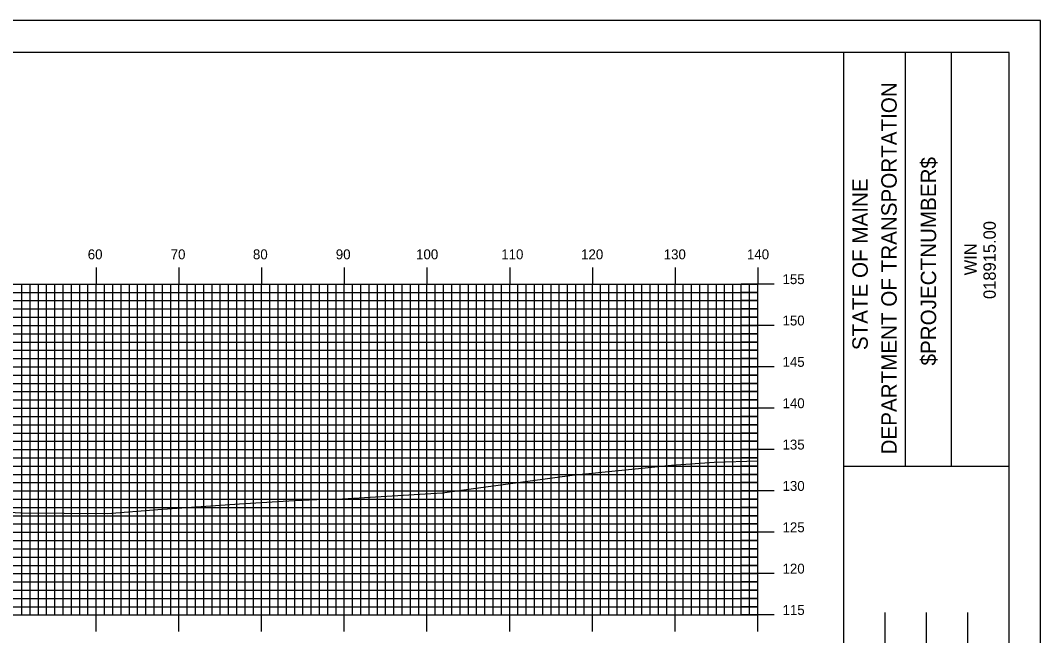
# Model space of a CAD drawing. Extents: x 851360 to 851703, y 364661 to 364881.
# Drawn here: x 851576.6 to 851699.9, y 364806.9 to 364881.3 of the extents above; entities that cross this region are included whole.
import ezdxf

# ---------------------------------------------------------------- set-up
doc = ezdxf.new("R2010")
doc.units = 0
for name, color, linetype in [('BORDER', 7, 'Continuous'), ('H_V ANNOTATION', 7, 'Continuous'), ('MAJOR', 7, 'Continuous'), ('MINOR', 7, 'Continuous'), ('PLOT BOUNDARY', 7, 'Continuous'), ('S_Roadway_Centerline', 7, 'Continuous')]:
    doc.layers.add(name, color=color, linetype=linetype)

msp = doc.modelspace()

# ---------------------------------------------------------------- linework, layer by layer
at = {"layer": 'BORDER'}
for p, q in [((851676.13, 364667.37), (851676.13, 364877.37)), ((851683.59, 364827.36), (851683.59, 364877.36)), ((851689.18, 364827.36), (851689.18, 364877.36)), ((851676.13, 364827.36), (851696.13, 364827.36)), ((851681.13, 364792.38), (851681.13, 364809.67)), ((851686.13, 364792.38), (851686.13, 364809.67)), ((851691.13, 364792.38), (851691.13, 364809.67))]:
    msp.add_line(p, q, dxfattribs=at)
msp.add_lwpolyline([(851376.13, 364667.37), (851696.13, 364667.37), (851696.13, 364877.37), (851376.13, 364877.37)], close=True, dxfattribs=at)
at = {"layer": 'MAJOR'}
for p, q in [((851585.73, 364851.37), (851585.73, 364849.37)), ((851595.73, 364851.37), (851595.73, 364849.37)), ((851605.73, 364851.37), (851605.73, 364849.37)), ((851615.73, 364851.37), (851615.73, 364849.37)), ((851625.73, 364851.37), (851625.73, 364849.37)), ((851635.73, 364851.37), (851635.73, 364849.37)), ((851645.73, 364851.37), (851645.73, 364849.37)), ((851655.73, 364851.37), (851655.73, 364849.37)), ((851665.73, 364851.37), (851665.73, 364849.37)), ((851385.73, 364849.37), (851665.73, 364849.37)), ((851385.73, 364849.37), (851665.73, 364849.37)), ((851585.73, 364809.37), (851585.73, 364849.37)), ((851595.73, 364809.37), (851595.73, 364849.37)), ((851605.73, 364809.37), (851605.73, 364849.37)), ((851615.73, 364809.37), (851615.73, 364849.37)), ((851625.73, 364809.37), (851625.73, 364849.37)), ((851635.73, 364809.37), (851635.73, 364849.37)), ((851645.73, 364809.37), (851645.73, 364849.37)), ((851655.73, 364809.37), (851655.73, 364849.37)), ((851667.73, 364849.37), (851663.72, 364849.37)), ((851665.73, 364809.37), (851665.73, 364849.37)), ((851665.73, 364809.37), (851665.73, 364849.37)), ((851385.73, 364844.37), (851665.73, 364844.37)), ((851667.73, 364844.37), (851663.72, 364844.37)), ((851385.73, 364839.37), (851665.73, 364839.37)), ((851667.73, 364839.37), (851663.72, 364839.37)), ((851385.73, 364834.37), (851665.73, 364834.37)), ((851667.73, 364834.37), (851663.72, 364834.37)), ((851385.73, 364829.37), (851665.73, 364829.37)), ((851667.73, 364829.37), (851663.72, 364829.37)), ((851385.73, 364824.37), (851665.73, 364824.37)), ((851667.73, 364824.37), (851663.72, 364824.37)), ((851385.73, 364819.37), (851665.73, 364819.37)), ((851667.73, 364819.37), (851663.72, 364819.37)), ((851385.73, 364814.37), (851665.73, 364814.37)), ((851667.73, 364814.37), (851663.72, 364814.37)), ((851385.73, 364809.37), (851665.73, 364809.37)), ((851385.73, 364809.37), (851665.73, 364809.37)), ((851585.73, 364807.37), (851585.73, 364809.37)), ((851595.73, 364807.37), (851595.73, 364809.37)), ((851605.73, 364807.37), (851605.73, 364809.37)), ((851615.73, 364807.37), (851615.73, 364809.37)), ((851625.73, 364807.37), (851625.73, 364809.37)), ((851635.73, 364807.37), (851635.73, 364809.37)), ((851645.73, 364807.37), (851645.73, 364809.37)), ((851655.73, 364807.37), (851655.73, 364809.37)), ((851667.73, 364809.37), (851663.72, 364809.37)), ((851665.73, 364807.37), (851665.73, 364809.37))]:
    msp.add_line(p, q, dxfattribs=at)
at = {"layer": 'MINOR'}
for p, q in [((851385.73, 364848.37), (851665.73, 364848.37)), ((851576.73, 364809.37), (851576.73, 364849.37)), ((851577.73, 364809.37), (851577.73, 364849.37)), ((851578.73, 364809.37), (851578.73, 364849.37)), ((851579.73, 364809.37), (851579.73, 364849.37)), ((851580.73, 364809.37), (851580.73, 364849.37)), ((851581.73, 364809.37), (851581.73, 364849.37)), ((851582.73, 364809.37), (851582.73, 364849.37)), ((851583.73, 364809.37), (851583.73, 364849.37)), ((851584.73, 364809.37), (851584.73, 364849.37)), ((851586.73, 364809.37), (851586.73, 364849.37)), ((851587.73, 364809.37), (851587.73, 364849.37)), ((851588.73, 364809.37), (851588.73, 364849.37)), ((851589.73, 364809.37), (851589.73, 364849.37)), ((851590.73, 364809.37), (851590.73, 364849.37)), ((851591.73, 364809.37), (851591.73, 364849.37)), ((851592.73, 364809.37), (851592.73, 364849.37)), ((851593.73, 364809.37), (851593.73, 364849.37)), ((851594.73, 364809.37), (851594.73, 364849.37)), ((851596.73, 364809.37), (851596.73, 364849.37)), ((851597.73, 364809.37), (851597.73, 364849.37)), ((851598.73, 364809.37), (851598.73, 364849.37)), ((851599.73, 364809.37), (851599.73, 364849.37)), ((851600.73, 364809.37), (851600.73, 364849.37)), ((851601.73, 364809.37), (851601.73, 364849.37)), ((851602.73, 364809.37), (851602.73, 364849.37)), ((851603.73, 364809.37), (851603.73, 364849.37)), ((851604.73, 364809.37), (851604.73, 364849.37)), ((851606.73, 364809.37), (851606.73, 364849.37)), ((851607.73, 364809.37), (851607.73, 364849.37)), ((851608.73, 364809.37), (851608.73, 364849.37)), ((851609.73, 364809.37), (851609.73, 364849.37)), ((851610.73, 364809.37), (851610.73, 364849.37)), ((851611.73, 364809.37), (851611.73, 364849.37)), ((851612.73, 364809.37), (851612.73, 364849.37)), ((851613.73, 364809.37), (851613.73, 364849.37)), ((851614.73, 364809.37), (851614.73, 364849.37)), ((851616.73, 364809.37), (851616.73, 364849.37)), ((851617.73, 364809.37), (851617.73, 364849.37)), ((851618.73, 364809.37), (851618.73, 364849.37)), ((851619.73, 364809.37), (851619.73, 364849.37)), ((851620.73, 364809.37), (851620.73, 364849.37)), ((851621.73, 364809.37), (851621.73, 364849.37)), ((851622.73, 364809.37), (851622.73, 364849.37)), ((851623.73, 364809.37), (851623.73, 364849.37)), ((851624.73, 364809.37), (851624.73, 364849.37)), ((851626.73, 364809.37), (851626.73, 364849.37)), ((851627.73, 364809.37), (851627.73, 364849.37)), ((851628.73, 364809.37), (851628.73, 364849.37)), ((851629.73, 364809.37), (851629.73, 364849.37)), ((851630.73, 364809.37), (851630.73, 364849.37)), ((851631.73, 364809.37), (851631.73, 364849.37)), ((851632.73, 364809.37), (851632.73, 364849.37)), ((851633.73, 364809.37), (851633.73, 364849.37)), ((851634.73, 364809.37), (851634.73, 364849.37)), ((851636.73, 364809.37), (851636.73, 364849.37)), ((851637.73, 364809.37), (851637.73, 364849.37)), ((851638.73, 364809.37), (851638.73, 364849.37)), ((851639.73, 364809.37), (851639.73, 364849.37)), ((851640.73, 364809.37), (851640.73, 364849.37)), ((851641.73, 364809.37), (851641.73, 364849.37)), ((851642.73, 364809.37), (851642.73, 364849.37)), ((851643.73, 364809.37), (851643.73, 364849.37)), ((851644.73, 364809.37), (851644.73, 364849.37)), ((851646.73, 364809.37), (851646.73, 364849.37)), ((851647.73, 364809.37), (851647.73, 364849.37)), ((851648.73, 364809.37), (851648.73, 364849.37)), ((851649.73, 364809.37), (851649.73, 364849.37)), ((851650.73, 364809.37), (851650.73, 364849.37)), ((851651.73, 364809.37), (851651.73, 364849.37)), ((851652.73, 364809.37), (851652.73, 364849.37)), ((851653.73, 364809.37), (851653.73, 364849.37)), ((851654.73, 364809.37), (851654.73, 364849.37)), ((851656.73, 364809.37), (851656.73, 364849.37)), ((851657.73, 364809.37), (851657.73, 364849.37)), ((851658.73, 364809.37), (851658.73, 364849.37)), ((851659.73, 364809.37), (851659.73, 364849.37)), ((851660.73, 364809.37), (851660.73, 364849.37)), ((851661.73, 364809.37), (851661.73, 364849.37)), ((851662.73, 364809.37), (851662.73, 364849.37)), ((851665.73, 364848.37), (851663.72, 364848.37)), ((851663.73, 364809.37), (851663.73, 364849.37)), ((851664.73, 364809.37), (851664.73, 364849.37)), ((851385.73, 364847.37), (851665.73, 364847.37)), ((851665.73, 364847.37), (851663.72, 364847.37)), ((851385.73, 364846.37), (851665.73, 364846.37)), ((851665.73, 364846.37), (851663.72, 364846.37)), ((851385.73, 364845.37), (851665.73, 364845.37)), ((851665.73, 364845.37), (851663.72, 364845.37)), ((851385.73, 364843.37), (851665.73, 364843.37)), ((851385.73, 364842.37), (851665.73, 364842.37)), ((851665.73, 364843.37), (851663.72, 364843.37)), ((851665.73, 364842.37), (851663.72, 364842.37)), ((851385.73, 364841.37), (851665.73, 364841.37)), ((851665.73, 364841.37), (851663.72, 364841.37)), ((851385.73, 364840.37), (851665.73, 364840.37)), ((851665.73, 364840.37), (851663.72, 364840.37)), ((851385.73, 364838.37), (851665.73, 364838.37)), ((851385.73, 364837.37), (851665.73, 364837.37)), ((851665.73, 364838.37), (851663.72, 364838.37)), ((851665.73, 364837.37), (851663.72, 364837.37)), ((851385.73, 364836.37), (851665.73, 364836.37)), ((851665.73, 364836.37), (851663.72, 364836.37)), ((851385.73, 364835.37), (851665.73, 364835.37)), ((851665.73, 364835.37), (851663.72, 364835.37)), ((851385.73, 364833.37), (851665.73, 364833.37)), ((851385.73, 364832.37), (851665.73, 364832.37)), ((851665.73, 364833.37), (851663.72, 364833.37)), ((851665.73, 364832.37), (851663.72, 364832.37)), ((851385.73, 364831.37), (851665.73, 364831.37)), ((851665.73, 364831.37), (851663.72, 364831.37)), ((851385.73, 364830.37), (851665.73, 364830.37)), ((851665.73, 364830.37), (851663.72, 364830.37)), ((851385.73, 364828.37), (851665.73, 364828.37)), ((851385.73, 364827.37), (851665.73, 364827.37)), ((851665.73, 364828.37), (851663.72, 364828.37)), ((851665.73, 364827.37), (851663.72, 364827.37)), ((851385.73, 364826.37), (851665.73, 364826.37)), ((851665.73, 364826.37), (851663.72, 364826.37)), ((851385.73, 364825.37), (851665.73, 364825.37)), ((851665.73, 364825.37), (851663.72, 364825.37)), ((851385.73, 364823.37), (851665.73, 364823.37)), ((851665.73, 364823.37), (851663.72, 364823.37)), ((851385.73, 364822.37), (851665.73, 364822.37)), ((851385.73, 364821.37), (851665.73, 364821.37)), ((851665.73, 364822.37), (851663.72, 364822.37)), ((851665.73, 364821.37), (851663.72, 364821.37)), ((851385.73, 364820.37), (851665.73, 364820.37)), ((851665.73, 364820.37), (851663.72, 364820.37)), ((851385.73, 364818.37), (851665.73, 364818.37)), ((851665.73, 364818.37), (851663.72, 364818.37)), ((851385.73, 364817.37), (851665.73, 364817.37)), ((851385.73, 364816.37), (851665.73, 364816.37)), ((851665.73, 364817.37), (851663.72, 364817.37)), ((851665.73, 364816.37), (851663.72, 364816.37)), ((851385.73, 364815.37), (851665.73, 364815.37)), ((851665.73, 364815.37), (851663.72, 364815.37)), ((851385.73, 364813.37), (851665.73, 364813.37)), ((851665.73, 364813.37), (851663.72, 364813.37)), ((851385.73, 364812.37), (851665.73, 364812.37)), ((851385.73, 364811.37), (851665.73, 364811.37)), ((851665.73, 364812.37), (851663.72, 364812.37)), ((851665.73, 364811.37), (851663.72, 364811.37)), ((851385.73, 364810.37), (851665.73, 364810.37)), ((851665.73, 364810.37), (851663.72, 364810.37))]:
    msp.add_line(p, q, dxfattribs=at)
at = {"layer": 'PLOT BOUNDARY'}
msp.add_lwpolyline([(851359.94, 364661.25), (851699.94, 364661.25), (851699.94, 364881.25), (851359.94, 364881.25)], close=True, dxfattribs=at)
at = {"layer": 'S_Roadway_Centerline'}
msp.add_lwpolyline([(851553.14, 364829.15), (851553.62, 364828.96), (851560.69, 364825.66), (851569.61, 364823.07), (851573.54, 364822), (851574.55, 364821.85), (851576.62, 364821.72), (851587.08, 364821.62), (851593.19, 364822.12), (851603.07, 364822.82), (851609.66, 364823.22), (851613.33, 364823.39), (851615.5, 364823.42), (851626.21, 364824.07), (851627.59, 364824.12), (851631.34, 364824.66), (851643.27, 364826.28), (851655.32, 364827.49), (851660.47, 364827.86), (851665.73, 364827.99)], dxfattribs=at)

# ---------------------------------------------------------------- texts
at = {"layer": 'BORDER'}
for s, height, p in [('DEPARTMENT OF TRANSPORTATION', 1.8635, (851682.54, 364828.78)), ('$PROJECTNUMBER$', 1.8635, (851687.31, 364839.53)), ('STATE OF MAINE', 1.8635, (851679.04, 364841.39)), ('018915.00', 1.491, (851694.52, 364847.57)), ('WIN', 1.491, (851692.2, 364850.43))]:
    msp.add_text(s, height=height, rotation=90, dxfattribs=at).set_placement(p)
at = {"layer": 'H_V ANNOTATION'}
for s, p in [('60', (851584.7, 364852.37)), ('70', (851594.73, 364852.37)), ('80', (851604.68, 364852.37)), ('90', (851614.7, 364852.37)), ('100', (851624.41, 364852.37)), ('110', (851634.71, 364852.37)), ('120', (851644.37, 364852.37)), ('130', (851654.36, 364852.37)), ('140', (851664.43, 364852.37)), ('155', (851668.73, 364849.37)), ('150', (851668.73, 364844.37)), ('145', (851668.73, 364839.37)), ('140', (851668.73, 364834.37)), ('135', (851668.73, 364829.37)), ('130', (851668.73, 364824.37)), ('125', (851668.73, 364819.37)), ('120', (851668.73, 364814.37)), ('115', (851668.73, 364809.37))]:
    msp.add_text(s, height=1.2, dxfattribs=at).set_placement(p)

doc.saveas('drawing.dxf')
